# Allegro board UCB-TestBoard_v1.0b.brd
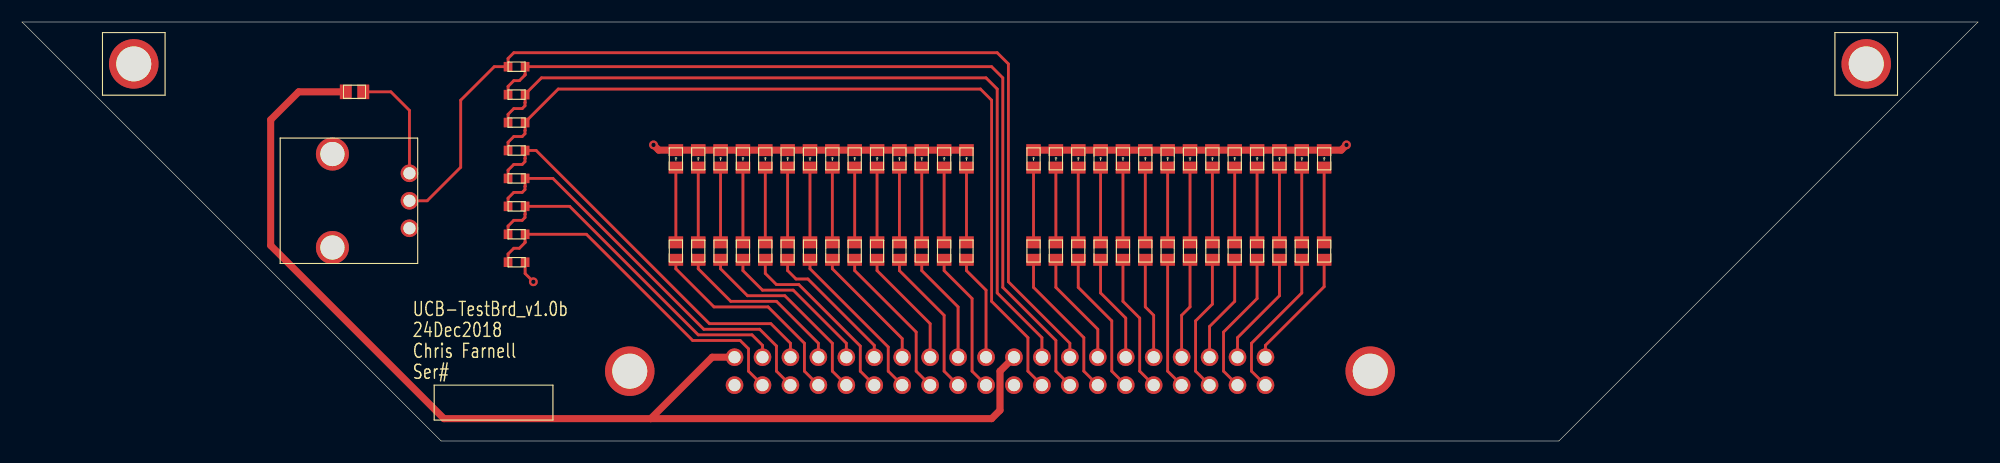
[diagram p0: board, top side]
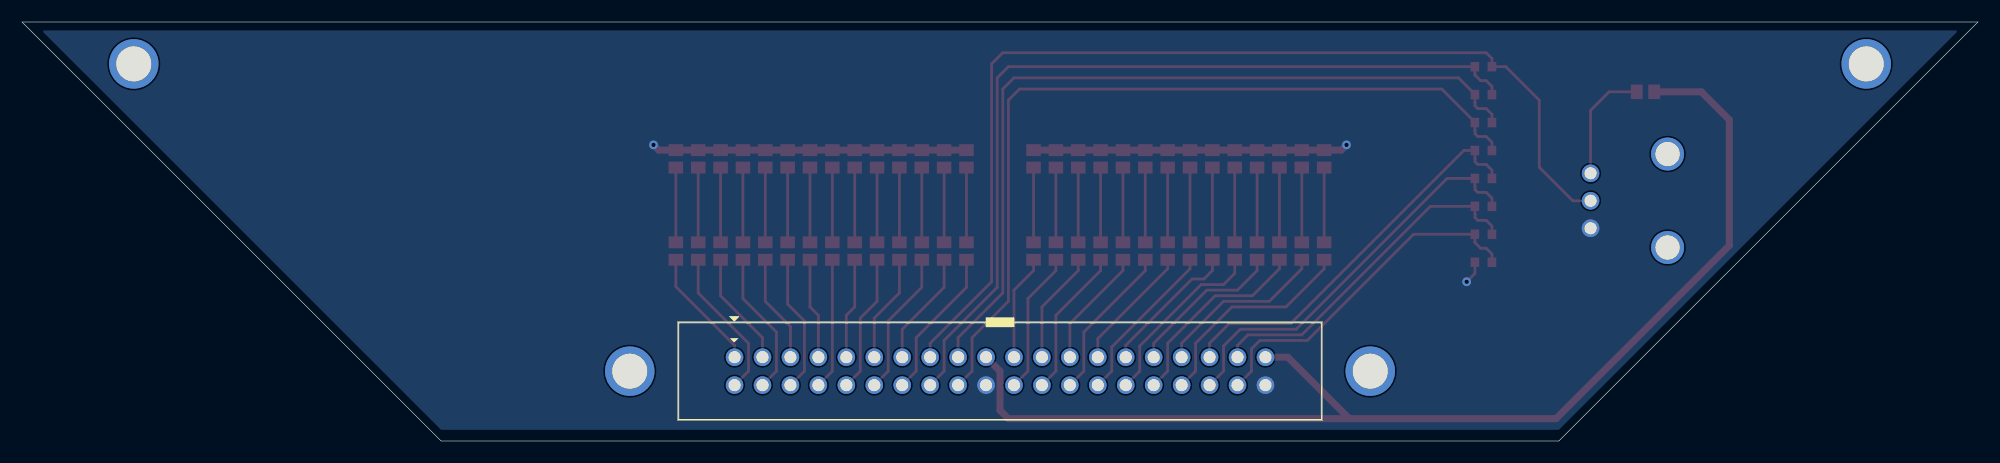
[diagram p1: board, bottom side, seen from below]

Outline 177.8 x 38.1 mm; copper layers: TOP, BOTTOM. Coordinates in mm from the lower left corner of the outline.
Outline path: 0,38.1 38.1,0 139.7,0 177.8,38.1 0,38.1

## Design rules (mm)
constraint set DEFAULT: min track width 0.152, pair gap 0.152

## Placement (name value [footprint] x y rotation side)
D1  LED-G  [LED_0805-GREEN]  118.36 25.65 270 top
D2  LED-G  [LED_0805-GREEN]  116.33 25.65 270 top
D3  LED-G  [LED_0805-GREEN]  114.3 25.65 270 top
D4  LED-G  [LED_0805-GREEN]  112.27 25.65 270 top
D5  LED-G  [LED_0805-GREEN]  110.24 25.65 270 top
D6  LED-G  [LED_0805-GREEN]  108.2 25.65 270 top
D7  LED-G  [LED_0805-GREEN]  106.17 25.65 270 top
D8  LED-G  [LED_0805-GREEN]  104.14 25.65 270 top
D9  LED-G  [LED_0805-GREEN]  102.11 25.65 270 top
D10  LED-G  [LED_0805-GREEN]  100.08 25.65 270 top
D11  LED-G  [LED_0805-GREEN]  98.04 25.65 270 top
D12  LED-G  [LED_0805-GREEN]  96.01 25.65 270 top
D13  LED-G  [LED_0805-GREEN]  93.98 25.65 270 top
D14  LED-G  [LED_0805-GREEN]  91.95 25.65 270 top
D15  LED-G  [LED_0805-GREEN]  85.85 25.65 270 top
D16  LED-G  [LED_0805-GREEN]  83.82 25.65 270 top
D17  LED-G  [LED_0805-GREEN]  81.79 25.65 270 top
D18  LED-G  [LED_0805-GREEN]  79.76 25.65 270 top
D19  LED-G  [LED_0805-GREEN]  77.72 25.65 270 top
D20  LED-G  [LED_0805-GREEN]  75.69 25.65 270 top
D21  LED-G  [LED_0805-GREEN]  73.66 25.65 270 top
D22  LED-G  [LED_0805-GREEN]  71.63 25.65 270 top
D23  LED-G  [LED_0805-GREEN]  69.6 25.65 270 top
D24  LED-G  [LED_0805-GREEN]  67.56 25.65 270 top
D25  LED-G  [LED_0805-GREEN]  65.53 25.65 270 top
D26  LED-G  [LED_0805-GREEN]  63.5 25.65 270 top
D27  LED-G  [LED_0805-GREEN]  61.47 25.65 270 top
D28  LED-G  [LED_0805-GREEN]  59.44 25.65 270 top
J1  SFH11-PBPC-D20-ST-BK  [40-IDC-F_MNT]  88.9 6.35 270 bottom
MECH1  Mech_Hole  [4-40_SCREW]  10.16 34.29 0 top
MECH2  Mech_Hole  [4-40_SCREW]  167.64 34.29 0 top
R1  220  [R_0805]  118.36 17.27 90 top
R2  220  [R_0805]  116.33 17.27 90 top
R3  220  [R_0805]  114.3 17.27 90 top
R4  220  [R_0805]  112.27 17.27 90 top
R5  220  [R_0805]  110.24 17.27 90 top
R6  220  [R_0805]  108.2 17.27 90 top
R7  220  [R_0805]  106.17 17.27 90 top
R8  220  [R_0805]  104.14 17.27 90 top
R9  220  [R_0805]  102.11 17.27 90 top
R10  220  [R_0805]  100.08 17.27 90 top
R11  220  [R_0805]  98.04 17.27 90 top
R12  220  [R_0805]  96.01 17.27 90 top
R13  220  [R_0805]  93.98 17.27 90 top
R14  220  [R_0805]  91.95 17.27 90 top
R15  220  [R_0805]  85.85 17.27 90 top
R16  220  [R_0805]  83.82 17.27 90 top
R17  220  [R_0805]  81.79 17.27 90 top
R18  220  [R_0805]  79.76 17.27 90 top
R19  220  [R_0805]  77.72 17.27 90 top
R20  220  [R_0805]  75.69 17.27 90 top
R21  220  [R_0805]  73.66 17.27 90 top
R22  220  [R_0805]  71.63 17.27 90 top
R23  220  [R_0805]  69.6 17.27 90 top
R24  220  [R_0805]  67.56 17.27 90 top
R25  220  [R_0805]  65.53 17.27 90 top
R26  220  [R_0805]  63.5 17.27 90 top
R27  220  [R_0805]  61.47 17.27 90 top
R28  220  [R_0805]  59.44 17.27 90 top
R29  10k  [R_0805]  30.23 31.75 0 top
R30  PTV09A-4020F-B103  [9MM_POT]  29.72 21.84 180 top
R31  100k  [R_0603]  44.96 34.04 0 top
R32  100k  [R_0603]  44.96 31.5 0 top
R33  100k  [R_0603]  44.96 28.96 0 top
R34  100k  [R_0603]  44.96 26.42 0 top
R35  100k  [R_0603]  44.96 23.88 0 top
R36  100k  [R_0603]  44.96 21.34 0 top
R37  100k  [R_0603]  44.96 18.8 0 top
R38  100k  [R_0603]  44.96 16.26 0 top

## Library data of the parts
D1-D28 = LED
J1 = Header_2x20
MECH1 MECH2 = Mech_Hole
R1-R29 R31-R38 = R-Standard
R30 = R-POT

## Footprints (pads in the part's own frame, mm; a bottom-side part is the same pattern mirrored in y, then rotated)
4-40_SCREW
  round 4.5 hole 3.175: 1(0,0)
9MM_POT
  round 3 hole 2.2: (1.5,4.25) (1.5,-4.25)
  round 1.6 hole 1.1: 1(-5.5,2.5) 2(-5.5,0) 3(-5.5,-2.5)
40-IDC-F_MNT
  round 4.5 hole 3.175: (0,-33.655) (0,33.655)
  round 1.6 hole 1.1: 1(-1.27,-24.13) 2(1.27,-24.13) 3(-1.27,-21.59) 4(1.27,-21.59) 5(-1.27,-19.05) 6(1.27,-19.05) 7(-1.27,-16.51) 8(1.27,-16.51) 9(-1.27,-13.97) 10(1.27,-13.97) 11(-1.27,-11.43) 12(1.27,-11.43) 13(-1.27,-8.89) 14(1.27,-8.89) 15(-1.27,-6.35) 16(1.27,-6.35) 17(-1.27,-3.81) 18(1.27,-3.81) 19(-1.27,-1.27) 20(1.27,-1.27) 21(-1.27,1.27) 22(1.27,1.27) 23(-1.27,3.81) 24(1.27,3.81) 25(-1.27,6.35) 26(1.27,6.35) 27(-1.27,8.89) 28(1.27,8.89) 29(-1.27,11.43) 30(1.27,11.43) 31(-1.27,13.97) 32(1.27,13.97) 33(-1.27,16.51) 34(1.27,16.51) 35(-1.27,19.05) 36(1.27,19.05) 37(-1.27,21.59) 38(1.27,21.59) 39(-1.27,24.13) 40(1.27,24.13)
LED_0805-GREEN
  rect 1.08x1.321 smd: 1(-0.794,0) 2(0.794,0)
R_0603
  rect 0.787x0.864 smd: 1(-0.775,0) 2(0.775,0)
R_0805
  rect 1.08x1.321 smd: 1(-0.794,0) 2(0.794,0)

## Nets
5V: J1.19 J1.39 R29.1
GND_SIGNAL: D1.1(CATHODE) D2.1(CATHODE) D3.1(CATHODE) D4.1(CATHODE) D5.1(CATHODE) D6.1(CATHODE) D7.1(CATHODE) D8.1(CATHODE) D9.1(CATHODE) D10.1(CATHODE) D11.1(CATHODE) D12.1(CATHODE) D13.1(CATHODE) D14.1(CATHODE) D15.1(CATHODE) D16.1(CATHODE) D17.1(CATHODE) D18.1(CATHODE) D19.1(CATHODE) D20.1(CATHODE) D21.1(CATHODE) D22.1(CATHODE) D23.1(CATHODE) D24.1(CATHODE) D25.1(CATHODE) D26.1(CATHODE) D27.1(CATHODE) D28.1(CATHODE) J1.20 J1.40 R30.1 R38.2
ADC-V1: J1.15 R30.2(WIPER) R31.1
ADC-V2: J1.16 R31.2 R32.1
ADC-V3: J1.17 R32.2 R33.1
ADC-V4: J1.18 R33.2 R34.1
ADC-V5: J1.35 R34.2 R35.1
ADC-V6: J1.36 R35.2 R36.1
ADC-V7: J1.37 R36.2 R37.1
ADC-V8: J1.38 R37.2 R38.1
LED1: J1.1 R1.1
LED2: J1.2 R2.1
LED3: J1.3 R3.1
LED4: J1.4 R4.1
LED5: J1.5 R5.1
LED6: J1.6 R6.1
LED7: J1.7 R7.1
LED8: J1.8 R8.1
LED9: J1.9 R9.1
LED10: J1.10 R10.1
LED11: J1.11 R11.1
LED12: J1.12 R12.1
LED13: J1.13 R13.1
LED14: J1.14 R14.1
LED15: J1.21 R15.1
LED16: J1.22 R16.1
LED17: J1.23 R17.1
LED18: J1.24 R18.1
LED19: J1.25 R19.1
LED20: J1.26 R20.1
LED21: J1.27 R21.1
LED22: J1.28 R22.1
LED23: J1.29 R23.1
LED24: J1.30 R24.1
LED25: J1.31 R25.1
LED26: J1.32 R26.1
LED27: J1.33 R27.1
LED28: J1.34 R28.1
N294916: D1.2 R1.2
N294970: D2.2 R2.2
N295024: D3.2 R3.2
N295078: D4.2 R4.2
N295138: D5.2 R5.2
N295192: D6.2 R6.2
N295246: D7.2 R7.2
N295300: D8.2 R8.2
N297354: D9.2 R9.2
N297404: D10.2 R10.2
N297454: D11.2 R11.2
N297504: D12.2 R12.2
N297554: D13.2 R13.2
N297604: D14.2 R14.2
N297654: D15.2 R15.2
N297704: D16.2 R16.2
N298162: D17.2 R17.2
N298212: D18.2 R18.2
N298262: D19.2 R19.2
N298312: D20.2 R20.2
N298362: D21.2 R21.2
N298412: D22.2 R22.2
N298462: D23.2 R23.2
N298512: D24.2 R24.2
N299934: D25.2 R25.2
N299984: D26.2 R26.2
N300034: D27.2 R27.2
N300084: D28.2 R28.2
N303443: R29.2 R30.3

Pads without a net: MECH1 1; MECH2 1

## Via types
v1: diameter 0.8, hole 0.4, TOP to BOTTOM, 3 vias

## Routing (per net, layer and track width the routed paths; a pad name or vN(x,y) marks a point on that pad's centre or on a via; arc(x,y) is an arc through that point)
5V: length 107.7
  TOP w0.635: 57.15,2.03 62.74,7.62 J1.39 ; 57.15,2.03 88.14,2.03 88.9,2.79 88.9,6.35 J1.19 ; 57.15,2.03 38.35,2.03 22.61,17.78 22.61,29.21 25.15,31.75 R29.1
GND_SIGNAL: length 59.4
  TOP w0.254: v1(46.48,14.48) 45.73,15.23 R38.2
  TOP w0.635: D14.1 D13.1 D12.1 D11.1 D10.1 D9.1 D8.1 D7.1 D6.1 D5.1 D4.1 D3.1 D2.1 D1.1 119.92,26.45 v1(120.4,26.92) ; D15.1 D16.1 D17.1 D18.1 D19.1 D20.1 D21.1 D22.1 D23.1 D24.1 D25.1 D26.1 D27.1 D28.1 57.88,26.45 v1(57.4,26.92)
ADC-V1: length 93.4
  TOP w0.254: R30.2 36.83,21.84 39.88,24.89 39.88,30.99 42.93,34.04 R31.1 44.18,34.79 44.7,35.31 88.65,35.31 89.66,34.29 89.66,14.48 95.25,8.89 J1.15
ADC-V2: length 77.8
  TOP w0.254: J1.16 93.98,6.35 93.98,9.14 89.15,13.97 89.15,33.02 88.14,34.04 R31.2 45.73,33.32 45.72,33.31 45.72,33.27 45.21,32.77 44.7,32.77 44.18,32.25 R32.1
ADC-V3: length 73.7
  TOP w0.254: R33.1 44.18,29.71 44.7,30.23 45.47,30.23 45.72,30.48 45.72,30.77 45.73,30.78 R32.2 45.73,31.53 47.22,33.02 87.63,33.02 88.65,32 88.65,13.46 92.71,9.4 J1.17
ADC-V4: length 75.5
  TOP w0.254: R34.1 44.18,27.17 44.7,27.69 45.47,27.69 45.72,27.94 45.72,28.23 45.73,28.24 R33.2 45.73,28.99 48.74,32 87.12,32 88.14,30.99 88.14,12.7 91.44,9.4 91.44,6.35 J1.18
ADC-V5: length 36.3
  TOP w0.254: R35.1 44.18,24.63 44.7,25.15 45.47,25.15 45.72,25.4 45.72,25.69 45.73,25.7 R34.2 46.74,26.42 62.48,10.67 68.07,10.67 69.85,8.89 J1.35
ADC-V6: length 36.9
  TOP w0.254: J1.36 68.58,6.35 68.58,8.64 67.06,10.16 61.98,10.16 48.26,23.88 R35.2 45.73,23.16 45.72,23.15 45.72,22.86 45.47,22.61 44.7,22.61 44.18,22.09 R36.1
ADC-V7: length 31.5
  TOP w0.254: R37.1 44.18,19.55 44.7,20.07 45.47,20.07 45.72,20.32 45.72,20.61 45.73,20.62 R36.2 49.78,21.34 61.47,9.65 66.36,9.65 67.31,8.7 J1.37
ADC-V8: length 31.9
  TOP w0.254: R38.1 44.18,17.01 44.7,17.53 45.21,17.53 45.72,18.03 45.72,18.07 45.73,18.08 R37.2 51.31,18.8 60.96,9.14 65.28,9.14 66.04,8.38 66.04,6.35 J1.38
LED1: length 11.1
  TOP w0.254: R1.1 118.36,14.03 113.03,8.7 J1.1
LED2: length 13.8
  TOP w0.254: R2.1 116.33,13.46 111.76,8.89 111.76,6.35 J1.2
LED3: length 10.4
  TOP w0.254: R3.1 114.3,13.21 110.49,9.4 J1.3
LED4: length 13.2
  TOP w0.254: R4.1 112.27,12.95 109.22,9.91 109.22,6.35 J1.4
LED5: length 9.8
  TOP w0.254: J1.5 107.95,10.41 110.24,12.7 R5.1
LED6: length 12.6
  TOP w0.254: J1.6 106.68,6.35 106.68,10.92 108.2,12.45 R6.1
LED7: length 9.2
  TOP w0.254: R7.1 106.17,12.19 105.41,11.43 J1.7
LED8: length 11.9
  TOP w0.254: R8.1 104.14,6.35 J1.8
LED9: length 9.2
  TOP w0.254: J1.9 102.87,11.43 102.11,12.19 R9.1
LED10: length 12.6
  TOP w0.254: R10.1 100.08,12.7 101.6,11.18 101.6,6.35 J1.10
LED11: length 9.8
  TOP w0.254: J1.11 100.33,11.18 98.04,13.46 R11.1
LED12: length 13.2
  TOP w0.254: J1.12 99.06,6.35 99.06,10.92 96.01,13.97 R12.1
LED13: length 10.4
  TOP w0.254: J1.13 97.79,10.16 93.98,13.97 R13.1
LED14: length 13.8
  TOP w0.254: J1.14 96.52,6.35 96.52,9.4 91.95,13.97 R14.1
LED15: length 9.6
  TOP w0.254: R15.1 85.85,15.49 87.63,13.72 J1.21
LED16: length 13
  TOP w0.254: R16.1 83.82,15.49 86.36,12.95 86.36,6.35 J1.22
LED17: length 10.2
  TOP w0.254: J1.23 85.09,12.19 81.79,15.49 R17.1
LED18: length 13.6
  TOP w0.254: R18.1 79.76,15.49 83.82,11.43 83.82,6.35 J1.24
LED19: length 10.9
  TOP w0.254: R19.1 77.72,15.49 82.55,10.67 J1.25
LED20: length 14.2
  TOP w0.254: J1.26 81.28,6.35 81.28,9.91 75.69,15.49 R20.1
LED21: length 11.5
  TOP w0.254: J1.27 80.01,9.31 73.66,15.66 R21.1
LED22: length 14.9
  TOP w0.254: J1.28 78.74,6.35 78.74,8.55 71.63,15.66 R22.1
LED23: length 12.8
  TOP w0.254: J1.29 77.47,8.7 71.44,14.73 70.36,14.73 69.6,15.49 R23.1
LED24: length 16.7
  TOP w0.254: R24.1 67.56,15.24 68.58,14.22 70.61,14.22 76.2,8.64 76.2,6.35 J1.30
LED25: length 14.4
  TOP w0.254: R25.1 65.53,15.49 67.31,13.72 70.1,13.72 74.93,8.89 J1.31
LED26: length 18.1
  TOP w0.254: R26.1 63.5,15.66 65.95,13.21 69.34,13.21 73.66,8.89 73.66,6.35 J1.32
LED27: length 15.8
  TOP w0.254: R27.1 61.47,15.66 64.43,12.7 68.58,12.7 72.39,8.89 J1.33
LED28: length 19.6
  TOP w0.254: R28.1 59.44,15.66 62.9,12.19 67.82,12.19 71.12,8.89 71.12,6.35 J1.34
N294916: length 6.8
  TOP w0.254: R1.2 D1.2
N294970: length 6.8
  TOP w0.254: R2.2 D2.2
N295024: length 6.8
  TOP w0.254: D3.2 R3.2
N295078: length 6.8
  TOP w0.254: R4.2 D4.2
N295138: length 6.8
  TOP w0.254: R5.2 D5.2
N295192: length 6.8
  TOP w0.254: R6.2 D6.2
N295246: length 6.8
  TOP w0.254: R7.2 D7.2
N295300: length 6.8
  TOP w0.254: D8.2 R8.2
N297354: length 6.8
  TOP w0.254: D9.2 R9.2
N297404: length 6.8
  TOP w0.254: D10.2 R10.2
N297454: length 6.8
  TOP w0.254: D11.2 R11.2
N297504: length 6.8
  TOP w0.254: R12.2 D12.2
N297554: length 6.8
  TOP w0.254: D13.2 R13.2
N297604: length 6.8
  TOP w0.254: R14.2 D14.2
N297654: length 6.8
  TOP w0.254: D15.2 R15.2
N297704: length 6.8
  TOP w0.254: R16.2 D16.2
N298162: length 6.8
  TOP w0.254: D17.2 R17.2
N298212: length 6.8
  TOP w0.254: R18.2 D18.2
N298262: length 6.8
  TOP w0.254: D19.2 R19.2
N298312: length 6.8
  TOP w0.254: R20.2 D20.2
N298362: length 6.8
  TOP w0.254: D21.2 R21.2
N298412: length 6.8
  TOP w0.254: D22.2 R22.2
N298462: length 6.8
  TOP w0.254: D23.2 R23.2
N298512: length 6.8
  TOP w0.254: D24.2 R24.2
N299934: length 6.8
  TOP w0.254: D25.2 R25.2
N299984: length 6.8
  TOP w0.254: R26.2 D26.2
N300034: length 6.8
  TOP w0.254: R27.2 D27.2
N300084: length 6.8
  TOP w0.254: R28.2 D28.2
N303443: length 10.6
  TOP w0.254: R30.3 35.22,30.06 33.53,31.75 R29.2

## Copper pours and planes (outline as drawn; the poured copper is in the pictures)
GND_SIGNAL on BOTTOM: 1.78,37.34 176.02,37.34 139.7,1.02 38.1,1.02

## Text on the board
Ref Des/Silkscreen Top: UCB-TestBrd_v1.0b | 24Dec2018 | Chris Farnell | Ser#
